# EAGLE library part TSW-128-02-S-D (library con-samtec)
THROUGH-HOLE .025" SQ POST HEADER Source: Samtec TSW.pdf
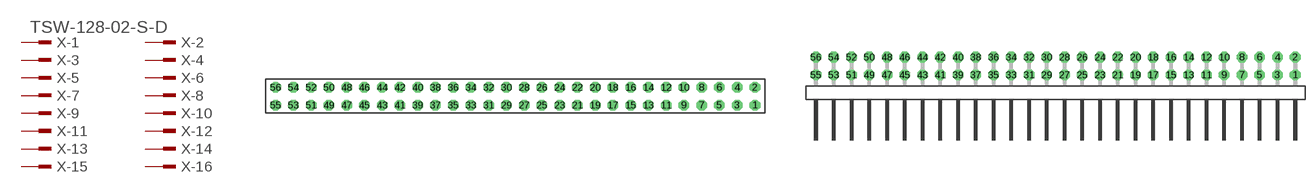
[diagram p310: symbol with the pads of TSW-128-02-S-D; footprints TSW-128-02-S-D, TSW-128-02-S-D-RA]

Designator prefix X; gates -1=MPINV -2=MPIN -3=MPIN -4=MPIN -5=MPIN -6=MPIN -7=MPIN -8=MPIN -9=MPIN -10=MPIN -11=MPIN -12=MPIN -13=MPIN -14=MPIN -15=MPIN -16=MPIN -17=MPIN -18=MPIN -19=MPIN -20=MPIN -21=MPIN -22=MPIN -23=MPIN -24=MPIN -25=MPIN -26=MPIN -27=MPIN -28=MPIN -29=MPIN -30=MPIN -31=MPIN -32=MPIN -33=MPIN -34=MPIN -35=MPIN -36=MPIN -37=MPIN -38=MPIN -39=MPIN -40=MPIN -41=MPIN -42=MPIN -43=MPIN -44=MPIN -45=MPIN -46=MPIN -47=MPIN -48=MPIN -49=MPIN -50=MPIN -51=MPIN -52=MPIN -53=MPIN -54=MPIN -55=MPIN -56=MPIN

## TSW-128-02-S-D (OC_FARNELL: unknown; OC_NEWARK: unknown)  [TSW-128-02-S-D]
1  -1:1  pas
2  -2:1  pas
3  -3:1  pas
4  -4:1  pas
5  -5:1  pas
6  -6:1  pas
7  -7:1  pas
8  -8:1  pas
9  -9:1  pas
10  -10:1  pas
11  -11:1  pas
12  -12:1  pas
13  -13:1  pas
14  -14:1  pas
15  -15:1  pas
16  -16:1  pas
17  -17:1  pas
18  -18:1  pas
19  -19:1  pas
20  -20:1  pas
21  -21:1  pas
22  -22:1  pas
23  -23:1  pas
24  -24:1  pas
25  -25:1  pas
26  -26:1  pas
27  -27:1  pas
28  -28:1  pas
29  -29:1  pas
30  -30:1  pas
31  -31:1  pas
32  -32:1  pas
33  -33:1  pas
34  -34:1  pas
35  -35:1  pas
36  -36:1  pas
37  -37:1  pas
38  -38:1  pas
39  -39:1  pas
40  -40:1  pas
41  -41:1  pas
42  -42:1  pas
43  -43:1  pas
44  -44:1  pas
45  -45:1  pas
46  -46:1  pas
47  -47:1  pas
48  -48:1  pas
49  -49:1  pas
50  -50:1  pas
51  -51:1  pas
52  -52:1  pas
53  -53:1  pas
54  -54:1  pas
55  -55:1  pas
56  -56:1  pas

## TSW-128-02-S-D-RA (OC_FARNELL: unknown; OC_NEWARK: unknown)  [TSW-128-02-S-D-RA]
Pads as for TSW-128-02-S-D

## Footprint TSW-128-02-S-D (pad centres in mm)
THROUGH-HOLE .025" SQ POST HEADER Source: Samtec TSW.pdf
drill 1 pad 1.5 octagon: 1 34.29,-1.27; 2 34.29,1.27; 3 31.75,-1.27; 4 31.75,1.27; 5 29.21,-1.27; 6 29.21,1.27; 7 26.67,-1.27; 8 26.67,1.27; 9 24.13,-1.27; 10 24.13,1.27; 11 21.59,-1.27; 12 21.59,1.27; 13 19.05,-1.27; 14 19.05,1.27; 15 16.51,-1.27; 16 16.51,1.27; 17 13.97,-1.27; 18 13.97,1.27; 19 11.43,-1.27; 20 11.43,1.27; 21 8.89,-1.27; 22 8.89,1.27; 23 6.35,-1.27; 24 6.35,1.27; 25 3.81,-1.27; 26 3.81,1.27; 27 1.27,-1.27; 28 1.27,1.27; 29 -1.27,-1.27; 30 -1.27,1.27; 31 -3.81,-1.27; 32 -3.81,1.27; 33 -6.35,-1.27; 34 -6.35,1.27; 35 -8.89,-1.27; 36 -8.89,1.27; 37 -11.43,-1.27; 38 -11.43,1.27; 39 -13.97,-1.27; 40 -13.97,1.27; 41 -16.51,-1.27; 42 -16.51,1.27; 43 -19.05,-1.27; 44 -19.05,1.27; 45 -21.59,-1.27; 46 -21.59,1.27; 47 -24.13,-1.27; 48 -24.13,1.27; 49 -26.67,-1.27; 50 -26.67,1.27; 51 -29.21,-1.27; 52 -29.21,1.27; 53 -31.75,-1.27; 54 -31.75,1.27; 55 -34.29,-1.27; 56 -34.29,1.27

## Footprint TSW-128-02-S-D-RA (pad centres in mm)
THROUGH-HOLE .025" SQ POST HEADER Source: Samtec TSW.pdf
drill 1 pad 1.5 octagon: 1 34.29,1.524; 2 34.29,4.064; 3 31.75,1.524; 4 31.75,4.064; 5 29.21,1.524; 6 29.21,4.064; 7 26.67,1.524; 8 26.67,4.064; 9 24.13,1.524; 10 24.13,4.064; 11 21.59,1.524; 12 21.59,4.064; 13 19.05,1.524; 14 19.05,4.064; 15 16.51,1.524; 16 16.51,4.064; 17 13.97,1.524; 18 13.97,4.064; 19 11.43,1.524; 20 11.43,4.064; 21 8.89,1.524; 22 8.89,4.064; 23 6.35,1.524; 24 6.35,4.064; 25 3.81,1.524; 26 3.81,4.064; 27 1.27,1.524; 28 1.27,4.064; 29 -1.27,1.524; 30 -1.27,4.064; 31 -3.81,1.524; 32 -3.81,4.064; 33 -6.35,1.524; 34 -6.35,4.064; 35 -8.89,1.524; 36 -8.89,4.064; 37 -11.43,1.524; 38 -11.43,4.064; 39 -13.97,1.524; 40 -13.97,4.064; 41 -16.51,1.524; 42 -16.51,4.064; 43 -19.05,1.524; 44 -19.05,4.064; 45 -21.59,1.524; 46 -21.59,4.064; 47 -24.13,1.524; 48 -24.13,4.064; 49 -26.67,1.524; 50 -26.67,4.064; 51 -29.21,1.524; 52 -29.21,4.064; 53 -31.75,1.524; 54 -31.75,4.064; 55 -34.29,1.524; 56 -34.29,4.064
